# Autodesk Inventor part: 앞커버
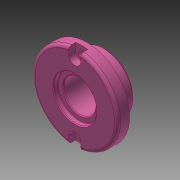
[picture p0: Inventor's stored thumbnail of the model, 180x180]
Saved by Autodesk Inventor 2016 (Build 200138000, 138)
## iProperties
Created: 2022-03
Part Number: 앞커버
Material: Generic
Document SubType Name: Modeling
Designer: mdu-01
Density: 1 g/cm^3
Appearance: 분홍색
Author: mdu-01
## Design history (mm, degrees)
sketch "스케치1"
  geometry: L1 (0, 0)-(0, -20); L2 (14, 0)-(28, 0); L3 (28, 0)-(28, -8); L4 (28, -8)-(19, -8); L5 (19, -8)-(19, -20); L6 (19, -20)-(10.5, -20); L7 (14, 0)-(14, -3); L8 (14, -3)-(10.5, -3); L9 (10.5, -3)-(10.5, -20)
  constraints: 18 end point, 5 perpendicular, 2 horizontal alignment, 2 parallel, 1 horizontal, 1 vertical
  dimensions: "d0" = 56 diameter of L3 L1; "d2" = 38 diameter of L5 L1; "d3" = 8 distance of L2.end L3.end; "d4" = 20 distance between parallel lines of L2 L6; "d5" = 21 diameter of L9 L1; "d6" = 28 diameter of L7 L1; "d7" = 3 distance of L2.start L7.end
revolve "회전1" sketch "스케치1" stored, may be unused: angle "d8" = 90 deg
fillet "모깎기1" dims "d9" = 0.5
chamfer "모따기1" distance "d10" = 0.5; stored, may be unused: second distance "d11" = 2, angle "d12" = 45 deg
chamfer "모따기2" distance "d13" = 1; stored, may be unused: second distance "d14" = 2, angle "d15" = 45 deg
fillet "모깎기2" dims "d32" = 2
sketch "스케치2" dims "d16" = 46
  geometry: 3 further points
  constraints: 2 vertical alignment, 1 coincident, 2 other
hole "구멍1" sketch "스케치2" at (0, 23) diameter "d18" = 4.5; stored, may be unused: countersink angle "d22" = 90 deg, drill point angle "d24" = 118 deg; dims "d19" = 6, "d20" = 8, "d21" = 4.6, "d23" = 8
sketch "스케치3"
  geometry: L1 (4, 23)-(4, 27.713); L2 (-4, 23)-(-4, 27.713); A1 r 4 centre (0, 23) between (-4, 23) and (4, 23) reference; A2 r 28 centre (0, 0) between (4, 27.713) and (-4, 27.713) reference; 1 further point
  constraints: 4 end point, 4 point on circle, 2 tangent, 1 parallel, 1 vertical
extrude "돌출1" cut sketch "스케치3" stored distance "d27" = 10; taper "d28" = 0 deg
fillet "모깎기3" dims "d33" = 0.3
node "솔리드1"
pattern_circular "원형 패턴1" dims angle "d30" = 360 deg
